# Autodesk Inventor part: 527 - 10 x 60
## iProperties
Created: 2005-09
Part Number: 527 - 10 x 60
Document SubType Name: Modeling
Designer: LEGERET Philippe
Manufacturer: Standard
Standards Organization: Custom
Catalog Web Link: www.traceparts.com
Description: Vis tête cylindrique a 6 pans creux (CHC)
Vendor: RABOURDIN INDUSTRIE
REFERENCE: 527 - 10 x 60
MATERIAL: Acier allié
Author: Trace Parts S.A.
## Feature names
1. Base1
